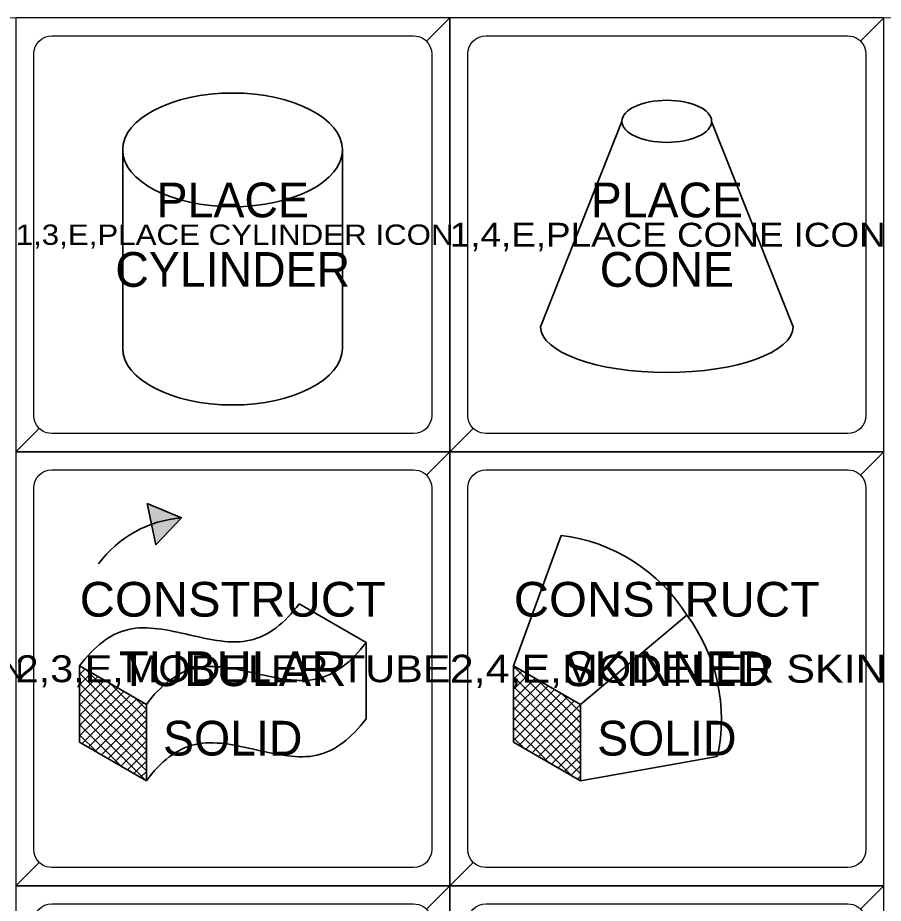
# Model space of a CAD drawing. Extents: x 95909.2 to 95923.3, y 90965 to 90971.2.
# Drawn here: x 95910.99 to 95912.186, y 90969.936 to 90971.16 of the extents above; entities that cross this region are included whole.
import ezdxf
from ezdxf.enums import TextEntityAlignment as Align

# ---------------------------------------------------------------- set-up
doc = ezdxf.new("R2010")
doc.units = 0
doc.header["$LTSCALE"] = 0.019
for name, color, linetype, lineweight in [('1', 7, 'Continuous', 25), ('10', 7, 'Continuous', 13), ('2', 7, 'Continuous', 25), ('3', 7, 'Continuous', 25), ('4', 7, 'Continuous', 25), ('6', 7, 'Continuous', 13)]:
    doc.layers.add(name, color=color, linetype=linetype, lineweight=lineweight)
doc.layers.add('5', color=7, linetype='Continuous')
doc.layers.add('63', color=7, linetype='Continuous')

msp = doc.modelspace()

# ---------------------------------------------------------------- hatches: boundary and pattern name
at = {"layer": '6'}
msp.add_hatch(color=256, dxfattribs=at).paths.add_polyline_path([(95911.1687, 90970.4886), (95911.2161, 90970.469), (95911.1807, 90970.4316)])

# ---------------------------------------------------------------- linework, layer by layer
at = {"layer": '1'}
for points in [[(95910.9868, 90970.5603), (95911.5868, 90970.5603), (95911.5868, 90971.1603), (95910.9868, 90971.1603)], [(95911.5868, 90970.5603), (95912.1868, 90970.5603), (95912.1868, 90971.1603), (95911.5868, 90971.1603)], [(95910.9868, 90969.9603), (95911.5868, 90969.9603), (95911.5868, 90970.5603), (95910.9868, 90970.5603)], [(95911.5868, 90969.9603), (95912.1868, 90969.9603), (95912.1868, 90970.5603), (95911.5868, 90970.5603)], [(95910.9868, 90969.3603), (95911.5868, 90969.3603), (95911.5868, 90969.9603), (95910.9868, 90969.9603)], [(95911.5868, 90969.3603), (95912.1868, 90969.3603), (95912.1868, 90969.9603), (95911.5868, 90969.9603)]]:
    msp.add_lwpolyline(points, close=True, dxfattribs=at)
at = {"layer": '10'}
msp.add_lwpolyline([(95909.7868, 90971.1603), (95915.7868, 90971.1603), (95915.7868, 90966.3603), (95909.7868, 90966.3603)], close=True, dxfattribs=at)
at = {"layer": '2'}
for points in [[(95910.9868, 90970.5603), (95911.5868, 90970.5603), (95911.5868, 90971.1603), (95910.9868, 90971.1603)], [(95911.5868, 90970.5603), (95912.1868, 90970.5603), (95912.1868, 90971.1603), (95911.5868, 90971.1603)], [(95910.9868, 90969.9603), (95911.5868, 90969.9603), (95911.5868, 90970.5603), (95910.9868, 90970.5603)], [(95911.5868, 90969.9603), (95912.1868, 90969.9603), (95912.1868, 90970.5603), (95911.5868, 90970.5603)], [(95910.9868, 90969.3603), (95911.5868, 90969.3603), (95911.5868, 90969.9603), (95910.9868, 90969.9603)], [(95911.5868, 90969.3603), (95912.1868, 90969.3603), (95912.1868, 90969.9603), (95911.5868, 90969.9603)]]:
    msp.add_lwpolyline(points, close=True, dxfattribs=at)
at = {"layer": '3'}
for points in [[(95911.5868, 90971.1603), (95910.9868, 90971.1603), (95910.9868, 90970.5603), (95911.0191, 90970.5926), (95911.016, 90970.5964), (95911.0137, 90970.6007), (95911.0123, 90970.6054), (95911.0118, 90970.6103), (95911.0118, 90971.1103), (95911.0123, 90971.1152), (95911.0137, 90971.1199), (95911.016, 90971.1242), (95911.0191, 90971.128), (95911.0191, 90971.128), (95911.0229, 90971.1311), (95911.0272, 90971.1334), (95911.0319, 90971.1348), (95911.0368, 90971.1353), (95911.5368, 90971.1353), (95911.5441, 90971.1342), (95911.5486, 90971.1323), (95911.5527, 90971.1296), (95911.5545, 90971.128)], [(95912.1868, 90971.1603), (95911.5868, 90971.1603), (95911.5868, 90970.5603), (95911.6191, 90970.5926), (95911.616, 90970.5964), (95911.6137, 90970.6007), (95911.6123, 90970.6054), (95911.6118, 90970.6103), (95911.6118, 90971.1103), (95911.6123, 90971.1152), (95911.6137, 90971.1199), (95911.616, 90971.1242), (95911.6191, 90971.128), (95911.6191, 90971.128), (95911.6229, 90971.1311), (95911.6272, 90971.1334), (95911.6319, 90971.1348), (95911.6368, 90971.1353), (95912.1368, 90971.1353), (95912.1441, 90971.1342), (95912.1486, 90971.1323), (95912.1527, 90971.1296), (95912.1545, 90971.128)], [(95911.5868, 90970.5603), (95910.9868, 90970.5603), (95910.9868, 90969.9603), (95911.0191, 90969.9926), (95911.016, 90969.9964), (95911.0137, 90970.0007), (95911.0123, 90970.0054), (95911.0118, 90970.0103), (95911.0118, 90970.5103), (95911.0123, 90970.5152), (95911.0137, 90970.5199), (95911.016, 90970.5242), (95911.0191, 90970.528), (95911.0191, 90970.528), (95911.0229, 90970.5311), (95911.0272, 90970.5334), (95911.0319, 90970.5348), (95911.0368, 90970.5353), (95911.5368, 90970.5353), (95911.5441, 90970.5342), (95911.5486, 90970.5323), (95911.5527, 90970.5296), (95911.5545, 90970.528)], [(95912.1868, 90970.5603), (95911.5868, 90970.5603), (95911.5868, 90969.9603), (95911.6191, 90969.9926), (95911.616, 90969.9964), (95911.6137, 90970.0007), (95911.6123, 90970.0054), (95911.6118, 90970.0103), (95911.6118, 90970.5103), (95911.6123, 90970.5152), (95911.6137, 90970.5199), (95911.616, 90970.5242), (95911.6191, 90970.528), (95911.6191, 90970.528), (95911.6229, 90970.5311), (95911.6272, 90970.5334), (95911.6319, 90970.5348), (95911.6368, 90970.5353), (95912.1368, 90970.5353), (95912.1441, 90970.5342), (95912.1486, 90970.5323), (95912.1527, 90970.5296), (95912.1545, 90970.528)], [(95911.5868, 90969.9603), (95910.9868, 90969.9603), (95910.9868, 90969.3603), (95911.0191, 90969.3926), (95911.016, 90969.3964), (95911.0137, 90969.4007), (95911.0123, 90969.4054), (95911.0118, 90969.4103), (95911.0118, 90969.9103), (95911.0123, 90969.9152), (95911.0137, 90969.9199), (95911.016, 90969.9242), (95911.0191, 90969.928), (95911.0191, 90969.928), (95911.0229, 90969.9311), (95911.0272, 90969.9334), (95911.0319, 90969.9348), (95911.0368, 90969.9353), (95911.5368, 90969.9353), (95911.5441, 90969.9342), (95911.5486, 90969.9323), (95911.5527, 90969.9296), (95911.5545, 90969.928)], [(95912.1868, 90969.9603), (95911.5868, 90969.9603), (95911.5868, 90969.3603), (95911.6191, 90969.3926), (95911.616, 90969.3964), (95911.6137, 90969.4007), (95911.6123, 90969.4054), (95911.6118, 90969.4103), (95911.6118, 90969.9103), (95911.6123, 90969.9152), (95911.6137, 90969.9199), (95911.616, 90969.9242), (95911.6191, 90969.928), (95911.6191, 90969.928), (95911.6229, 90969.9311), (95911.6272, 90969.9334), (95911.6319, 90969.9348), (95911.6368, 90969.9353), (95912.1368, 90969.9353), (95912.1441, 90969.9342), (95912.1486, 90969.9323), (95912.1527, 90969.9296), (95912.1545, 90969.928)]]:
    msp.add_lwpolyline(points, close=True, dxfattribs=at)
at = {"layer": '4'}
for points in [[(95910.9868, 90970.5603), (95911.5868, 90970.5603), (95911.5868, 90971.1603), (95911.5545, 90971.128), (95911.5576, 90971.1242), (95911.5599, 90971.1199), (95911.5613, 90971.1152), (95911.5618, 90971.1103), (95911.5618, 90970.6103), (95911.5613, 90970.6054), (95911.5599, 90970.6007), (95911.5576, 90970.5964), (95911.5545, 90970.5926), (95911.5545, 90970.5926), (95911.5507, 90970.5895), (95911.5464, 90970.5872), (95911.5417, 90970.5858), (95911.5368, 90970.5853), (95911.0368, 90970.5853), (95911.0295, 90970.5864), (95911.025, 90970.5883), (95911.0209, 90970.591), (95911.0191, 90970.5926)], [(95911.5868, 90970.5603), (95912.1868, 90970.5603), (95912.1868, 90971.1603), (95912.1545, 90971.128), (95912.1576, 90971.1242), (95912.1599, 90971.1199), (95912.1613, 90971.1152), (95912.1618, 90971.1103), (95912.1618, 90970.6103), (95912.1613, 90970.6054), (95912.1599, 90970.6007), (95912.1576, 90970.5964), (95912.1545, 90970.5926), (95912.1545, 90970.5926), (95912.1507, 90970.5895), (95912.1464, 90970.5872), (95912.1417, 90970.5858), (95912.1368, 90970.5853), (95911.6368, 90970.5853), (95911.6295, 90970.5864), (95911.625, 90970.5883), (95911.6209, 90970.591), (95911.6191, 90970.5926)], [(95910.9868, 90969.9603), (95911.5868, 90969.9603), (95911.5868, 90970.5603), (95911.5545, 90970.528), (95911.5576, 90970.5242), (95911.5599, 90970.5199), (95911.5613, 90970.5152), (95911.5618, 90970.5103), (95911.5618, 90970.0103), (95911.5613, 90970.0054), (95911.5599, 90970.0007), (95911.5576, 90969.9964), (95911.5545, 90969.9926), (95911.5545, 90969.9926), (95911.5507, 90969.9895), (95911.5464, 90969.9872), (95911.5417, 90969.9858), (95911.5368, 90969.9853), (95911.0368, 90969.9853), (95911.0295, 90969.9864), (95911.025, 90969.9883), (95911.0209, 90969.991), (95911.0191, 90969.9926)], [(95911.5868, 90969.9603), (95912.1868, 90969.9603), (95912.1868, 90970.5603), (95912.1545, 90970.528), (95912.1576, 90970.5242), (95912.1599, 90970.5199), (95912.1613, 90970.5152), (95912.1618, 90970.5103), (95912.1618, 90970.0103), (95912.1613, 90970.0054), (95912.1599, 90970.0007), (95912.1576, 90969.9964), (95912.1545, 90969.9926), (95912.1545, 90969.9926), (95912.1507, 90969.9895), (95912.1464, 90969.9872), (95912.1417, 90969.9858), (95912.1368, 90969.9853), (95911.6368, 90969.9853), (95911.6295, 90969.9864), (95911.625, 90969.9883), (95911.6209, 90969.991), (95911.6191, 90969.9926)], [(95910.9868, 90969.3603), (95911.5868, 90969.3603), (95911.5868, 90969.9603), (95911.5545, 90969.928), (95911.5576, 90969.9242), (95911.5599, 90969.9199), (95911.5613, 90969.9152), (95911.5618, 90969.9103), (95911.5618, 90969.4103), (95911.5613, 90969.4054), (95911.5599, 90969.4007), (95911.5576, 90969.3964), (95911.5545, 90969.3926), (95911.5545, 90969.3926), (95911.5507, 90969.3895), (95911.5464, 90969.3872), (95911.5417, 90969.3858), (95911.5368, 90969.3853), (95911.0368, 90969.3853), (95911.0295, 90969.3864), (95911.025, 90969.3883), (95911.0209, 90969.391), (95911.0191, 90969.3926)], [(95911.5868, 90969.3603), (95912.1868, 90969.3603), (95912.1868, 90969.9603), (95912.1545, 90969.928), (95912.1576, 90969.9242), (95912.1599, 90969.9199), (95912.1613, 90969.9152), (95912.1618, 90969.9103), (95912.1618, 90969.4103), (95912.1613, 90969.4054), (95912.1599, 90969.4007), (95912.1576, 90969.3964), (95912.1545, 90969.3926), (95912.1545, 90969.3926), (95912.1507, 90969.3895), (95912.1464, 90969.3872), (95912.1417, 90969.3858), (95912.1368, 90969.3853), (95911.6368, 90969.3853), (95911.6295, 90969.3864), (95911.625, 90969.3883), (95911.6209, 90969.391), (95911.6191, 90969.3926)]]:
    msp.add_lwpolyline(points, close=True, dxfattribs=at)
at = {"layer": '6', "lineweight": 35}
for p, q in [((95911.8248, 90971.017), (95911.7123, 90970.733)), ((95911.9487, 90971.017), (95912.0613, 90970.733)), ((95911.1347, 90970.9776), (95911.1347, 90970.7036)), ((95911.4385, 90970.9776), (95911.4385, 90970.7036)), ((95911.675, 90970.2642), (95911.7407, 90970.4447)), ((95911.7674, 90970.211), (95911.9145, 90970.3343)), ((95911.7674, 90970.1055), (95911.9565, 90970.1388))]:
    msp.add_line(p, q, dxfattribs=at)
at = {"layer": '6'}
for p, q in [((95911.675, 90970.2638), (95911.7674, 90970.1714)), ((95911.675, 90970.2599), (95911.6777, 90970.2626)), ((95911.075, 90970.2523), (95911.0826, 90970.2598)), ((95911.075, 90970.2381), (95911.0915, 90970.2547)), ((95911.075, 90970.254), (95911.1674, 90970.1616)), ((95911.075, 90970.224), (95911.1005, 90970.2495)), ((95911.0843, 90970.2589), (95911.1674, 90970.1757)), ((95911.675, 90970.2457), (95911.6867, 90970.2575)), ((95911.675, 90970.2316), (95911.6957, 90970.2523)), ((95911.675, 90970.2497), (95911.7674, 90970.1573)), ((95911.075, 90970.2099), (95911.1095, 90970.2443)), ((95911.075, 90970.2399), (95911.1674, 90970.1475)), ((95911.075, 90970.1957), (95911.1185, 90970.2392)), ((95911.1176, 90970.2397), (95911.1674, 90970.1899)), ((95911.675, 90970.2174), (95911.7047, 90970.2471)), ((95911.675, 90970.2033), (95911.7136, 90970.2419)), ((95911.675, 90970.1892), (95911.7226, 90970.2368)), ((95911.7075, 90970.2455), (95911.7674, 90970.1856)), ((95911.075, 90970.1816), (95911.1274, 90970.234)), ((95911.075, 90970.1674), (95911.1364, 90970.2288)), ((95911.075, 90970.2257), (95911.1674, 90970.1333)), ((95911.675, 90970.2356), (95911.7674, 90970.1432)), ((95911.675, 90970.175), (95911.7316, 90970.2316)), ((95911.675, 90970.1609), (95911.7406, 90970.2264)), ((95911.7408, 90970.2263), (95911.7674, 90970.1997)), ((95911.0786, 90970.1568), (95911.1454, 90970.2237)), ((95911.0875, 90970.1517), (95911.1544, 90970.2185)), ((95911.0965, 90970.1465), (95911.1633, 90970.2133)), ((95911.1509, 90970.2205), (95911.1674, 90970.204)), ((95911.675, 90970.2214), (95911.7674, 90970.129)), ((95911.6827, 90970.1544), (95911.7495, 90970.2213)), ((95911.6917, 90970.1493), (95911.7585, 90970.2161)), ((95911.075, 90970.2116), (95911.1674, 90970.1192)), ((95911.1054, 90970.1413), (95911.1674, 90970.2033)), ((95911.675, 90970.2073), (95911.7674, 90970.1149)), ((95911.7006, 90970.1441), (95911.7674, 90970.2108)), ((95911.075, 90970.1974), (95911.1663, 90970.1061)), ((95911.1144, 90970.1361), (95911.1674, 90970.1891)), ((95911.675, 90970.1931), (95911.7561, 90970.112)), ((95911.7096, 90970.1389), (95911.7674, 90970.1967)), ((95911.075, 90970.1833), (95911.1328, 90970.1255)), ((95911.675, 90970.179), (95911.7226, 90970.1314)), ((95911.7186, 90970.1337), (95911.7674, 90970.1826)), ((95911.075, 90970.1691), (95911.0993, 90970.1449)), ((95911.1234, 90970.1309), (95911.1674, 90970.175)), ((95911.675, 90970.1648), (95911.6891, 90970.1508)), ((95911.7275, 90970.1285), (95911.7674, 90970.1684)), ((95911.1323, 90970.1258), (95911.1674, 90970.1608)), ((95911.7365, 90970.1234), (95911.7674, 90970.1543)), ((95911.1413, 90970.1206), (95911.1674, 90970.1467)), ((95911.7454, 90970.1182), (95911.7674, 90970.1401)), ((95911.1503, 90970.1154), (95911.1674, 90970.1326)), ((95911.1592, 90970.1102), (95911.1674, 90970.1184)), ((95911.7544, 90970.113), (95911.7674, 90970.126)), ((95911.7634, 90970.1078), (95911.7674, 90970.1119))]:
    msp.add_line(p, q, dxfattribs=at)
at = {"layer": '6', "lineweight": 35}
for points in [[(95911.1687, 90970.4886), (95911.2161, 90970.469), (95911.1807, 90970.4316)], [(95911.1674, 90970.1055), (95911.1674, 90970.211), (95911.075, 90970.2642), (95911.075, 90970.1589)], [(95911.7674, 90970.1055), (95911.7674, 90970.211), (95911.675, 90970.2642), (95911.675, 90970.1589)]]:
    msp.add_lwpolyline(points, close=True, dxfattribs=at)
msp.add_lwpolyline([(95911.471, 90970.191), (95911.471, 90970.2965), (95911.3785, 90970.3498)], dxfattribs=at)
for centre, radius, start, end in [((95911.22798, 90970.31231), 0.15709, 94.32654, 143.6635), ((95911.7114, 90970.2065), 0.24, 32.18702, 82.99454), ((95911.7222, 90970.19076), 0.24, 347.50035, 36.74583)]:
    msp.add_arc(centre, radius, start, end, dxfattribs=at)
for centre, major_axis, ratio in [((95911.28658, 90970.97761), (0.15188, 0), 0.517312), ((95911.88676, 90971.01705), (0.06198, 0), 0.470325)]:
    msp.add_ellipse(centre, major_axis=major_axis, ratio=ratio, dxfattribs=at)
for centre, major_axis, ratio, start_param, end_param in [((95911.88676, 90970.73301), (0.17448, 0), 0.362655, 3.1415927, 6.2831853), ((95911.28658, 90970.70351), (0.15188, 0), 0.517312, 3.1416618, 6.2831028)]:
    msp.add_ellipse(centre, major_axis=major_axis, ratio=ratio, start_param=start_param, end_param=end_param, dxfattribs=at)
for points in [[(95911.075, 90970.2642), (95911.0948, 90970.2906), (95911.1392, 90970.327), (95911.2268, 90970.3071), (95911.3143, 90970.2872), (95911.3587, 90970.3235), (95911.3785, 90970.3498)], [(95911.1674, 90970.211), (95911.1873, 90970.2374), (95911.2317, 90970.2736), (95911.3192, 90970.2537), (95911.4067, 90970.2339), (95911.4511, 90970.2701), (95911.471, 90970.2965)], [(95911.1674, 90970.1055), (95911.1873, 90970.1319), (95911.2317, 90970.1681), (95911.3192, 90970.1482), (95911.4067, 90970.1284), (95911.4511, 90970.1646), (95911.471, 90970.191)]]:
    msp.add_open_spline(points, degree=3, dxfattribs=at)

# ---------------------------------------------------------------- texts
at = {"layer": '5'}
for s, p in [('PLACE', (95911.28685, 90970.8843)), ('PLACE', (95911.88685, 90970.8843)), ('CYLINDER', (95911.2868, 90970.7883)), ('CONE', (95911.8868, 90970.7883)), ('SKINNED', (95911.88685, 90970.2363)), ('SOLID', (95911.2868, 90970.1403)), ('SOLID', (95911.8868, 90970.1403))]:
    msp.add_text(s, height=0.048, dxfattribs=at).set_placement(p, align=Align.CENTER)
at = {"layer": '5', "width": 1.05}
for s, p in [('CONSTRUCT', (95911.2868, 90970.3323)), ('CONSTRUCT', (95911.8868, 90970.3323)), ('TUBULAR', (95911.28685, 90970.2363))]:
    msp.add_text(s, height=0.048, dxfattribs=at).set_placement(p, align=Align.CENTER)
at = {"layer": '63', "width": 1.15}
for s, height, p in [('1,3,E,PLACE CYLINDER ICON', 0.0281, (95910.9868, 90970.8463)), ('1,4,E,PLACE CONE ICON', 0.0331, (95911.5868, 90970.8437)), ('2,2,E,MODELER REVOLUTION', 0.0277, (95910.3868, 90970.2465)), ('2,3,E,MODELER TUBE', 0.0372, (95910.9868, 90970.2417)), ('2,4,E,MODELER SKIN', 0.0386, (95911.5868, 90970.241))]:
    msp.add_text(s, height=height, dxfattribs=at).set_placement(p)

doc.saveas('drawing.dxf')
